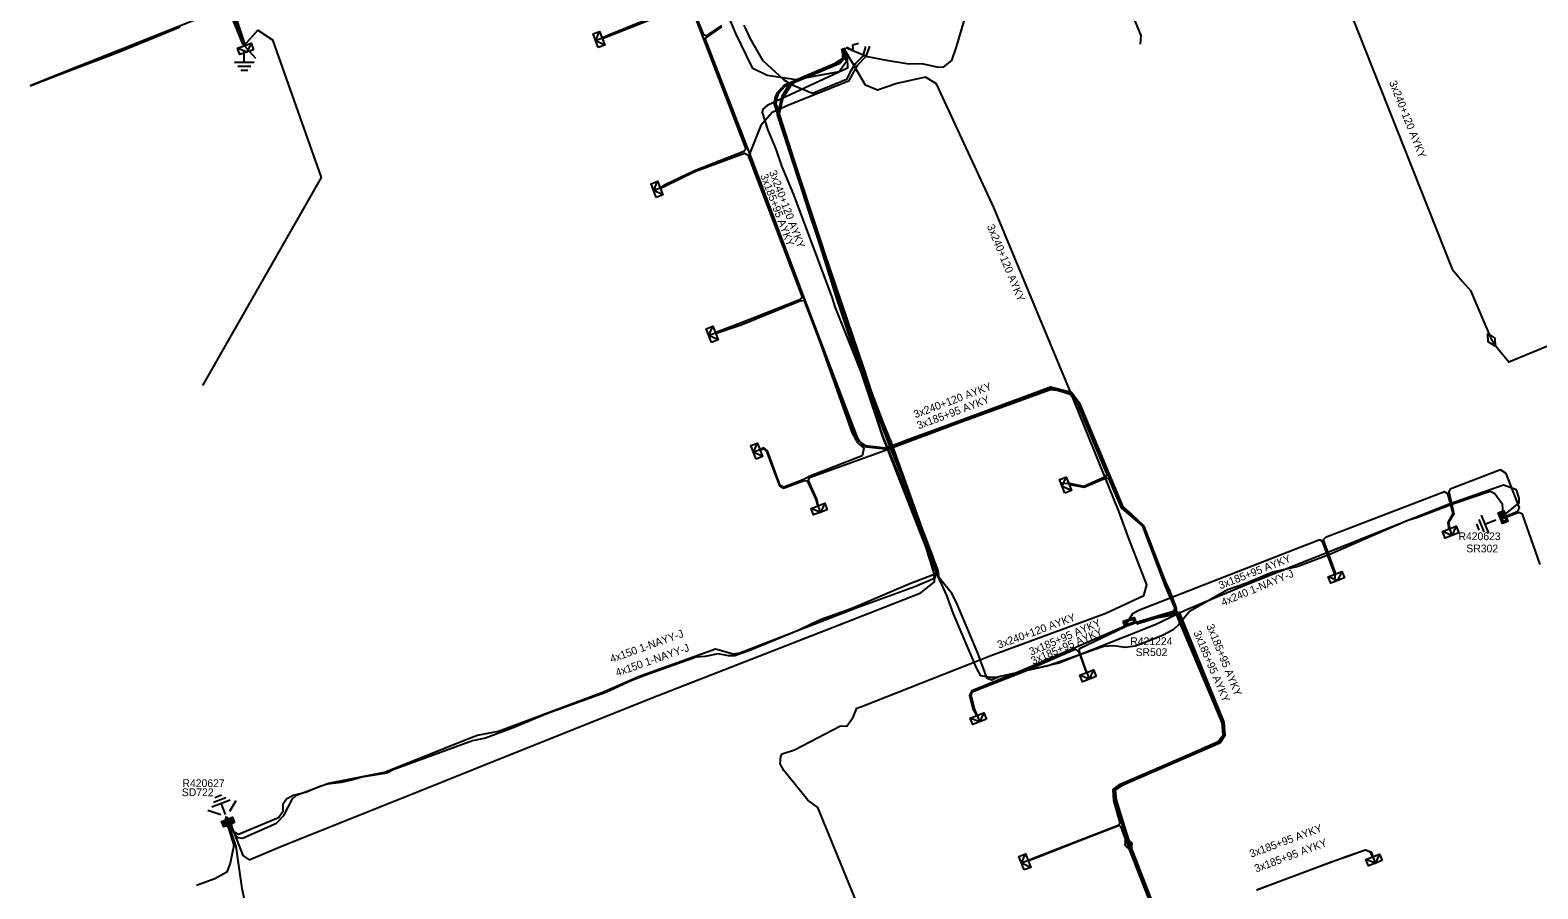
# Model space of a CAD drawing. Extents: x -540028 to -538776, y -1157064 to -1155670.
# Drawn here: x -540028.2 to -539834.1, y -1156040.4 to -1155929.9 of the extents above; entities that cross this region are included whole.
import ezdxf

# ---------------------------------------------------------------- set-up
doc = ezdxf.new("R2010")
doc.units = 0
for name, color, linetype in [('Vrstva 15', 7, 'Continuous'), ('Vrstva 19', 7, 'Continuous'), ('Vrstva 2', 7, 'Continuous'), ('Vrstva 28', 7, 'Continuous'), ('Vrstva 29', 7, 'Continuous'), ('Vrstva 30', 7, 'Continuous'), ('Vrstva 31', 7, 'Continuous'), ('Vrstva 5', 7, 'Continuous'), ('Vrstva 59', 7, 'Continuous'), ('Vrstva 6', 7, 'Continuous'), ('Vrstva 9', 7, 'Continuous')]:
    doc.layers.add(name, color=color, linetype=linetype)

# ---------------------------------------------------------------- blocks, each defined once
blk = doc.blocks.new('17')
at = {"layer": 'Vrstva 2'}
blk.add_lwpolyline([(-1.875, 0), (0, 0.9375), (1.875, 0), (0, -0.9375)], close=True, dxfattribs=at)
blk = doc.blocks.new('132')
at = {"layer": 'Vrstva 2'}
for points in [[(-1.5, 1.5), (1.5, 1.5), (1.5, 0), (-1.5, 0)], [(-1.1, 1.2), (1.1, 1.2), (1.1, 0.3), (-1.1, 0.3)]]:
    blk.add_lwpolyline(points, close=True, dxfattribs=at)
blk = doc.blocks.new('23')
at = {"layer": 'Vrstva 2'}
blk.add_lwpolyline([(1.875, -1.8), (-1.875, -1.8), (-1.875, 0), (1.875, 0)], close=True, dxfattribs=at)
blk.add_lwpolyline([(1.875, 0), (0, -1.8), (-1.875, 0)], dxfattribs=at)
blk = doc.blocks.new('11')
at = {"layer": 'Vrstva 2'}
for p, q in [((0, -4.3), (0, -1.3)), ((-2.5, -4.3), (2.5, -4.3)), ((-1.7, -5.3), (1.7, -5.3)), ((-0.9, -6.3), (0.9, -6.3))]:
    blk.add_line(p, q, dxfattribs=at)

msp = doc.modelspace()

# ---------------------------------------------------------------- linework, layer by layer
at = {"layer": 'Vrstva 5'}
for points in [[(-539923.21, -1155932.13), (-539920.48, -1155933.29), (-539917.96, -1155933.77), (-539915.09, -1155934.22), (-539913.44, -1155934.2), (-539911.31, -1155934.66), (-539910.61, -1155934.6), (-539909.58, -1155933.81), (-539908.94, -1155932.04), (-539907.91, -1155928.58), (-539907.39, -1155927.03), (-539906.62, -1155924.35), (-539904.52, -1155923.13), (-539902.28, -1155922.05), (-539874.21, -1155910.19), (-539872.95, -1155910.4), (-539871.83, -1155912.86), (-539873.27, -1155917.34)], [(-539864.72, -1155912.09), (-539858.4, -1155927.24), (-539845.14, -1155960.66), (-539843.86, -1155962.22), (-539842.78, -1155963.39), (-539840.09, -1155969.77)], [(-539873.57, -1155917.46), (-539874.09, -1155917.04), (-539877.68, -1155918.43), (-539881.42, -1155919.95), (-539886.16, -1155922.38), (-539886.77, -1155923.05), (-539887.27, -1155924.13), (-539886.55, -1155927.38), (-539885.24, -1155930.57)], [(-539941.93, -1155919.51), (-539937.39, -1155930.32), (-539935.25, -1155934.75), (-539933.32, -1155935.67), (-539929.58, -1155936.26), (-539924.07, -1155935.23), (-539923.12, -1155933.89), (-539923.63, -1155932.32)], [(-540002.3, -1155927.48), (-540000.64, -1155931.61), (-540000.64, -1155931.88), (-540000.83, -1155931.68), (-540002.5, -1155927.53)], [(-539943.66, -1155926.44), (-539953.55, -1155930.43), (-539954.55, -1155930.88), (-539954.57, -1155930.93), (-539954.51, -1155930.95), (-539943.67, -1155926.69)], [(-539943.15, -1155926.79), (-539936.08, -1155945.19), (-539936.32, -1155945.51), (-539942.68, -1155948), (-539946.45, -1155949.81), (-539947.07, -1155950.17), (-539947.1, -1155950.22), (-539947.04, -1155950.24), (-539946.42, -1155949.92), (-539942.64, -1155948.07), (-539936.26, -1155945.71), (-539935.8, -1155945.95), (-539928.83, -1155964.25), (-539929.04, -1155964.58), (-539936.76, -1155967.61), (-539939.93, -1155968.81), (-539939.99, -1155968.88), (-539939.89, -1155968.9), (-539936.69, -1155967.81), (-539928.99, -1155964.7), (-539928.59, -1155964.75), (-539926.53, -1155970.16), (-539922.4, -1155981.76), (-539921.73, -1155982.93), (-539920.87, -1155983.76), (-539921.1, -1155984.67), (-539927.91, -1155987.35), (-539928.63, -1155987.72), (-539931.17, -1155988.73), (-539931.64, -1155988.5), (-539933.29, -1155984.03), (-539933.76, -1155983.65), (-539934.23, -1155983.87), (-539934.26, -1155983.91), (-539934.2, -1155983.93), (-539933.75, -1155983.79), (-539933.41, -1155984.11), (-539931.74, -1155988.56), (-539931.21, -1155988.85), (-539928.55, -1155987.84), (-539928.17, -1155987.91), (-539927.06, -1155990.29), (-539926.86, -1155991.07), (-539926.8, -1155991.12), (-539926.75, -1155991.04), (-539926.95, -1155990.27), (-539928.02, -1155987.86), (-539927.87, -1155987.48), (-539918.1, -1155983.96), (-539908.71, -1155980.43), (-539896.84, -1155976.14), (-539896.01, -1155976.23), (-539894.33, -1155976.73), (-539893.44, -1155977.96), (-539889.59, -1155987.09), (-539889.79, -1155987.4), (-539892.57, -1155988.64), (-539894.38, -1155988.24), (-539894.5, -1155988.29)], [(-539939.2, -1155929.31), (-539941.17, -1155930.62), (-539941.49, -1155930.5), (-539943.08, -1155926.61)], [(-540008.91, -1155929.5), (-540013.7, -1155931.47), (-540016.97, -1155932.82), (-540024.56, -1155935.68), (-540028.19, -1155937.12)], [(-539885.8, -1156006.24), (-539885.73, -1156006.15), (-539883.25, -1156005.41), (-539880.93, -1156004.8), (-539880.62, -1156004.29), (-539881.44, -1156002.1), (-539882.01, -1156000.96), (-539884.82, -1155993.72), (-539887.66, -1155991.28), (-539893.31, -1155977.89), (-539893.62, -1155977.46), (-539894.24, -1155976.6), (-539895.98, -1155976.08), (-539896.86, -1155975.98), (-539908.76, -1155980.29), (-539918.15, -1155983.82), (-539920.91, -1155983.51), (-539921.63, -1155982.56), (-539923.73, -1155977.05), (-539928.51, -1155964.45), (-539935.45, -1155946.09), (-539941.33, -1155930.97), (-539939.17, -1155929.47)], [(-539920.68, -1155932), (-539921.01, -1155933.25), (-539922.01, -1155934.24), (-539922.67, -1155935.36), (-539923.12, -1155936.25), (-539927.48, -1155938.03), (-539930.1, -1155936.98), (-539931.19, -1155936.29), (-539933.83, -1155933.83), (-539935.5, -1155930.94), (-539936.28, -1155929.23)], [(-540002.86, -1156031.48), (-540001.9, -1156033.37), (-540001.46, -1156033.81), (-540000.89, -1156033.88), (-539996.48, -1156031.96), (-539995.54, -1156030.98), (-539994.43, -1156028.84), (-539993.92, -1156028.37), (-539989.78, -1156026.81), (-539982.58, -1156025.41), (-539971.29, -1156020.9), (-539970.62, -1156020.66), (-539967.91, -1156020.14), (-539954.61, -1156015.14), (-539951.06, -1156013.6), (-539949.9, -1156013.11), (-539939.99, -1156009.53), (-539937.72, -1156010.17), (-539936.86, -1156010.06), (-539928.3, -1156006.73), (-539927.2, -1156006.3), (-539922.98, -1156004.69), (-539921.87, -1156004.27), (-539914.32, -1156001.49), (-539911.72, -1156000.38), (-539911.48, -1155999.5), (-539913.12, -1155995.28), (-539917.5, -1155983.04), (-539918.6, -1155980.42), (-539920.06, -1155976.46), (-539920.99, -1155973.68), (-539927.61, -1155954.25), (-539932.37, -1155939.41), (-539932.29, -1155938.6), (-539932, -1155937.9), (-539931.12, -1155936.94), (-539924.07, -1155933.98), (-539923.6, -1155933.49), (-539923.58, -1155932.92), (-539923.7, -1155932.31)], [(-539923.36, -1155932.19), (-539923.02, -1155933.47), (-539922.98, -1155934.78), (-539933.33, -1155939.61), (-539933.89, -1155940.04), (-539933.98, -1155940.47), (-539933.23, -1155942.76), (-539932.23, -1155945.21), (-539931.49, -1155947.35), (-539929.9, -1155951.17), (-539925.01, -1155964.27), (-539924.6, -1155965.5), (-539919.91, -1155977.31), (-539918.8, -1155980.31), (-539917.52, -1155983.59), (-539915.31, -1155989.07), (-539912.04, -1155997.59), (-539911.57, -1155999.4), (-539911.7, -1155999.9), (-539914.96, -1156001.16), (-539922, -1156004.16), (-539923.11, -1156004.61), (-539926.4, -1156005.74), (-539927.6, -1156006.29), (-539929.36, -1156007.18), (-539935.35, -1156009.66), (-539937.49, -1156010.45), (-539938.33, -1156010.42), (-539939.62, -1156010.19), (-539941.3, -1156010.5), (-539942.46, -1156010.62), (-539949.06, -1156012.95), (-539950.77, -1156013.6), (-539954.09, -1156015.14), (-539961.61, -1156017.84), (-539966.03, -1156019.7), (-539969.58, -1156021.02), (-539971.25, -1156021.37), (-539981.48, -1156025.1), (-539982.28, -1156025.54), (-539985.45, -1156026.03), (-539986.65, -1156026.41), (-539988.15, -1156026.75), (-539989.91, -1156026.96), (-539990.9, -1156027.27), (-539992.62, -1156027.98), (-539994.33, -1156028.42), (-539995.19, -1156028.9), (-539995.67, -1156029.56), (-539995.67, -1156030.49), (-539996.24, -1156031.28), (-540001.37, -1156033.41), (-540001.93, -1156033.12), (-540002.69, -1156032.12), (-540002.82, -1156031.42)], [(-539920.15, -1155931.97), (-539920.61, -1155933.3), (-539921.76, -1155934.44), (-539922.85, -1155936.45), (-539930.67, -1155939.59), (-539932.7, -1155940.49), (-539934.14, -1155942.16), (-539935.53, -1155945.58), (-539935.59, -1155946.31), (-539931.97, -1155955.71), (-539926.81, -1155969.18), (-539922.75, -1155980.21), (-539921.77, -1155982.63), (-539920.72, -1155983.34), (-539918.1, -1155983.67), (-539916.23, -1155982.95), (-539915.56, -1155982.71), (-539910.16, -1155980.73), (-539896.84, -1155975.82), (-539894.17, -1155976.51), (-539893.16, -1155977.83), (-539887.55, -1155991.23), (-539886.4, -1155992.22), (-539884.98, -1155993.56), (-539882.11, -1156001.17), (-539874.7, -1156019.01), (-539874.55, -1156020.64), (-539875.2, -1156021.54), (-539887.83, -1156027.04), (-539888.69, -1156027.65), (-539888.61, -1156029.01), (-539887.02, -1156034.15), (-539886.66, -1156035.08), (-539882.13, -1156046.77)], [(-539838.94, -1155992.7), (-539838.57, -1155992), (-539838.67, -1155990.93), (-539839.67, -1155989.57), (-539840.28, -1155989.26), (-539845.08, -1155990.9), (-539849.71, -1155992.66), (-539850.84, -1155993.03), (-539856.32, -1155995.35), (-539860.88, -1155997.4), (-539864.98, -1155998.94), (-539868.24, -1155999.66), (-539871.7, -1156001.11), (-539874.07, -1156001.95), (-539878.95, -1156004.71), (-539880.38, -1156006.42), (-539881.07, -1156007.09), (-539882.43, -1156007.81), (-539884.71, -1156008.71), (-539885.96, -1156009.18), (-539887.23, -1156009.36), (-539888.69, -1156009.16), (-539889.99, -1156009.23), (-539892.61, -1156010.13), (-539897.15, -1156011.72), (-539903.5, -1156013.14), (-539904.43, -1156013.57), (-539905.02, -1156013.34), (-539906.23, -1156010.07), (-539908.89, -1156003.8), (-539909.5, -1156002.45), (-539911.18, -1156000.39), (-539911.3, -1155999.43), (-539912.94, -1155995.21), (-539917.32, -1155982.96), (-539918.42, -1155980.34), (-539919.88, -1155976.4), (-539920.81, -1155973.62), (-539927.43, -1155954.19), (-539932.17, -1155939.39), (-539932.09, -1155938.66), (-539931.82, -1155938), (-539931, -1155937.1), (-539923.95, -1155934.14), (-539923.4, -1155933.57), (-539923.38, -1155932.9), (-539923.51, -1155932.23)], [(-539920.99, -1156044.18), (-539926.8, -1156029.97), (-539928.09, -1156029.01), (-539931.17, -1156025.2), (-539931.64, -1156024.33), (-539931.56, -1156023.35), (-539931.38, -1156023.04), (-539929.82, -1156022.55), (-539923.9, -1156019.44), (-539923.08, -1156019.48), (-539922.27, -1156018.32), (-539921.78, -1156017.16), (-539921.06, -1156016.91), (-539904.39, -1156010.35), (-539889.73, -1156004.95), (-539884.83, -1156002.66), (-539884.47, -1156001.31), (-539886.77, -1155995.32), (-539888.06, -1155991.82), (-539894.41, -1155976.16), (-539898.67, -1155965.95), (-539904.15, -1155952.71), (-539911.52, -1155936.82), (-539912.96, -1155935.94), (-539916.65, -1155936.75), (-539919.11, -1155937.63), (-539920.66, -1155936.96), (-539923.45, -1155932.23)], [(-539923.09, -1155932.09), (-539922.53, -1155932.4), (-539922.27, -1155932.3), (-539922.32, -1155931.8)], [(-539830.05, -1155969.43), (-539837.85, -1155972.64), (-539839.26, -1155970.91), (-539840.09, -1155969.77)], [(-539894.5, -1155988.29), (-539894.4, -1155988.37), (-539892.52, -1155988.72), (-539889.71, -1155987.53), (-539889.38, -1155987.6), (-539887.78, -1155991.38), (-539885.02, -1155993.73), (-539882.07, -1156001.57), (-539880.86, -1156004.34), (-539881.06, -1156004.73), (-539885.82, -1156006.13), (-539885.83, -1156006.16)], [(-539838.94, -1155992.76), (-539836.68, -1155991.82), (-539836.48, -1155991.37), (-539838.19, -1155986.97), (-539838.95, -1155986.48), (-539845.41, -1155988.96), (-539845.59, -1155989.28), (-539844.93, -1155992.14), (-539845.61, -1155993.27), (-539845.5, -1155993.94), (-539845.51, -1155994.1), (-539845.56, -1155993.94), (-539845.66, -1155993.25), (-539845.02, -1155992.12), (-539845.71, -1155989.56), (-539846.14, -1155989.3), (-539861.44, -1155995.21), (-539861.74, -1155995.49), (-539860.22, -1155999.76), (-539860.23, -1155999.9)], [(-539833.81, -1155998.68), (-539836.11, -1155992.19), (-539836.57, -1155991.96), (-539838.89, -1155992.88)], [(-539860.23, -1155999.9), (-539860.32, -1155999.82), (-539861.85, -1155995.72), (-539862.19, -1155995.48), (-539865.4, -1155996.73), (-539885.39, -1156004.56), (-539886.31, -1156005.01), (-539887.27, -1156006.59), (-539893.2, -1156009.18), (-539900.4, -1156012.27), (-539907, -1156014.93), (-539907.29, -1156015.48), (-539906.84, -1156017.26), (-539906.34, -1156018.1), (-539906.32, -1156018.1), (-539906.31, -1156018.08), (-539906.64, -1156017.2), (-539907.05, -1156015.53), (-539906.96, -1156015.08), (-539900.29, -1156012.44), (-539893.68, -1156009.59), (-539893.22, -1156009.91), (-539892.25, -1156012.56), (-539892.2, -1156012.59), (-539892.17, -1156012.53), (-539892.59, -1156011.39), (-539893.13, -1156009.87), (-539893.14, -1156009.49), (-539887.28, -1156006.7)], [(-539883.66, -1156043.14), (-539886.91, -1156034.8), (-539887.77, -1156032.5), (-539887.99, -1156032.29), (-539893.1, -1156034.26), (-539898.61, -1156036.42), (-539899.68, -1156036.81), (-539899.75, -1156036.79), (-539899.73, -1156036.72), (-539898.65, -1156036.32), (-539893.14, -1156034.17), (-539888.03, -1156032.2), (-539887.87, -1156031.92), (-539888.71, -1156029.04), (-539888.78, -1156027.64), (-539887.88, -1156026.95), (-539880.33, -1156023.68), (-539875.26, -1156021.45), (-539874.62, -1156020.6), (-539874.77, -1156019.04), (-539880.66, -1156005.12), (-539883.23, -1156005.6), (-539885.62, -1156006.32), (-539885.72, -1156006.45)], [(-539885.76, -1156006.34), (-539885.65, -1156006.23), (-539883.25, -1156005.48), (-539880.3, -1156004.8), (-539874.53, -1156018.98), (-539874.42, -1156020.7), (-539875.07, -1156021.69), (-539887.72, -1156027.18), (-539888.54, -1156027.71), (-539888.41, -1156028.97), (-539887.55, -1156031.77), (-539886.51, -1156035), (-539882.48, -1156045.43)], [(-540003.04, -1156031.53), (-540002.84, -1156032.07), (-540002, -1156034.83), (-540002.45, -1156037.1), (-540002.91, -1156038.29), (-540004.45, -1156039.14), (-540006.79, -1156039.98)], [(-540002.68, -1156032.01), (-540002.92, -1156031.47)], [(-540002, -1156063.03), (-539999.22, -1156062.13), (-539997.22, -1156060.88), (-539996.66, -1156059.27), (-539997.35, -1156055.47), (-539998.23, -1156051.74), (-539998.43, -1156049.71), (-539999.71, -1156046.23), (-540000.93, -1156040.38), (-540001.68, -1156034.96), (-540002.68, -1156032.01)], [(-539870.33, -1156040.53), (-539858.6, -1156036.19), (-539856.32, -1156035.39), (-539855.59, -1156035.68), (-539855.38, -1156036.28), (-539855.38, -1156036.3), (-539855.4, -1156036.28), (-539855.66, -1156035.7), (-539856.34, -1156035.45), (-539858.58, -1156036.24), (-539860.58, -1156036.96), (-539870.3, -1156040.6)]]:
    msp.add_lwpolyline(points, dxfattribs=at)
at = {"layer": 'Vrstva 59'}
for points in [[(-540000.64, -1155931.88), (-539998.9, -1155929.91), (-539997, -1155931.15), (-539990.73, -1155948.86), (-540006.04, -1155975.62)], [(-539954.57, -1155930.93), (-539955.51, -1155931.29)], [(-539922.32, -1155931.8), (-539921.57, -1155931.58)], [(-539885.24, -1155930.57), (-539885.32, -1155931.68)], [(-540000.64, -1155931.88), (-539999.2, -1155933.49)], [(-539947.1, -1155950.22), (-539948.04, -1155950.57)], [(-539939.99, -1155968.88), (-539940.92, -1155969.24)], [(-539934.26, -1155983.91), (-539935.19, -1155984.27)], [(-539894.5, -1155988.29), (-539895.61, -1155988.19)], [(-539926.8, -1155991.12), (-539926.44, -1155992.05)], [(-539845.51, -1155994.1), (-539845.14, -1155995.03)], [(-539860.23, -1155999.9), (-539860.33, -1156001.01)], [(-539892.2, -1156012.59), (-539891.84, -1156013.52)], [(-539906.32, -1156018.1), (-539905.95, -1156019.03)], [(-540003.67, -1156030.89), (-540005.32, -1156030.34)], [(-540002.52, -1156030.44), (-540001.7, -1156029.05)], [(-539855.38, -1156036.3), (-539855.02, -1156037.23)], [(-539899.75, -1156036.79), (-539900.68, -1156037.16)]]:
    msp.add_lwpolyline(points, dxfattribs=at)
at = {"layer": 'Vrstva 9'}
for points in [[(-540028.21, -1155937.02), (-540024.81, -1155935.64), (-540016.61, -1155932.38), (-540004.35, -1155927.48)], [(-540002.15, -1155927.87), (-540000.6, -1155931.77), (-540000.56, -1155931.79), (-540000.53, -1155931.74), (-540001.9, -1155927.61)], [(-540002.17, -1156032.72), (-540000.85, -1156036.12), (-540000.01, -1156036.69), (-539995.44, -1156034.76), (-539978.98, -1156028.2), (-539966.71, -1156023.28), (-539947.51, -1156015.56), (-539922.32, -1156005.75), (-539913.54, -1156002.3), (-539911.81, -1156000.91), (-539911.83, -1155999.82), (-539912.86, -1155996.5), (-539918.46, -1155982.25), (-539924.45, -1155964.18), (-539926.39, -1155957.99), (-539932, -1155940.78), (-539931.39, -1155938.38), (-539930.53, -1155936.96), (-539929.65, -1155936.28), (-539924.57, -1155934.15), (-539923.49, -1155933.45), (-539923.36, -1155932.83), (-539923.57, -1155932.3)], [(-539838.9, -1155992.68), (-539836.52, -1155990.73), (-539836.51, -1155990.12), (-539836.87, -1155989.05), (-539838.53, -1155988.45), (-539845.52, -1155990.89), (-539871.84, -1156001.38), (-539879.45, -1156004.57), (-539883.37, -1156006.44), (-539895.8, -1156011.38), (-539903.85, -1156013.23), (-539904.59, -1156013.2), (-539905.82, -1156013.01), (-539906.37, -1156011.98), (-539909.35, -1156005.01), (-539910.19, -1156002.68), (-539911.54, -1155999.74), (-539914.4, -1155991.84), (-539918.39, -1155982.26), (-539924.37, -1155964.15), (-539926.16, -1155957.8), (-539931.77, -1155940.73), (-539931.26, -1155938.56), (-539930.3, -1155937.04), (-539929.41, -1155936.29), (-539924.51, -1155934.28), (-539923.43, -1155933.46), (-539923.26, -1155932.73), (-539923.53, -1155932.26)], [(-540002.71, -1156031.31), (-540002.17, -1156032.72)]]:
    msp.add_lwpolyline(points, dxfattribs=at)

# ---------------------------------------------------------------- block references
at = {"layer": 'Vrstva 15', "xscale": 0.5, "yscale": 0.5}
msp.add_blockref('11', (-540000.64, -1155931.88), dxfattribs=at)
at = {"layer": 'Vrstva 15'}
for p, xscale, yscale, rotation in [((-539838.94, -1155992.7), 0.49999999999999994, 0.5000000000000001, -68.48933332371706), ((-540002.86, -1156031.48), 0.5, 0.49999999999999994, -158.7815499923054)]:
    msp.add_blockref('11', p, dxfattribs=dict(at, xscale=xscale, yscale=yscale, rotation=rotation))
at = {"layer": 'Vrstva 19', "xscale": 0.5, "yscale": 0.5}
for p, rotation in [((-539840.09, -1155969.77), -60.901705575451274), ((-540002.68, -1156032), -71.4348555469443), ((-539886.81, -1156034.68), -68.71983336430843)]:
    msp.add_blockref('17', p, dxfattribs=dict(at, rotation=rotation))
at = {"layer": 'Vrstva 28'}
for p, xscale, yscale, rotation in [((-539838.94, -1155992.7), 0.49999999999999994, 0.5000000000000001, -68.48933332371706), ((-539886.55, -1156006.44), 0.5, 0.5, 19.766536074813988), ((-540002.86, -1156031.48), 0.5, 0.5000000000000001, -158.26336167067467)]:
    msp.add_blockref('132', p, dxfattribs=dict(at, xscale=xscale, yscale=yscale, rotation=rotation))
at = {"layer": 'Vrstva 31'}
for p, xscale, yscale, rotation in [((-540000.64, -1155931.88), 0.5, 0.49999999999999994, 19.86837223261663), ((-539954.57, -1155930.93), 0.5, 0.5, -69.01018334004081), ((-539947.1, -1155950.22), 0.49999999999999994, 0.5000000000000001, -69.29247776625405), ((-539939.99, -1155968.88), 0.49999999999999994, 0.5000000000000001, -68.92459724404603), ((-539934.26, -1155983.91), 0.5, 0.5, -68.94524173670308), ((-539894.5, -1155988.29), 0.5, 0.5, -68.58318614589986), ((-539926.8, -1155991.12), 0.49999999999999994, 0.5000000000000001, 21.146627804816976), ((-539845.51, -1155994.1), 0.5, 0.5, 21.605747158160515), ((-539860.23, -1155999.9), 0.5, 0.5, 21.547544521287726), ((-539892.2, -1156012.59), 0.5, 0.49999999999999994, 21.428786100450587), ((-539906.32, -1156018.1), 0.5, 0.5000000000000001, 21.425341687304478), ((-539899.75, -1156036.79), 0.49999999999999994, 0.5000000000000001, -68.27450564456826), ((-539855.38, -1156036.3), 0.49999999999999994, 0.5000000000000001, 21.60288329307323)]:
    msp.add_blockref('23', p, dxfattribs=dict(at, xscale=xscale, yscale=yscale, rotation=rotation))

# ---------------------------------------------------------------- texts
at = {"layer": 'Vrstva 29'}
for s, p in [('R420623', (-539844.34, -1155995.54)), ('R421224', (-539886.59, -1156009.05))]:
    msp.add_text(s, height=1, dxfattribs=at).set_placement(p)
msp.add_text('R420627', height=1, rotation=359.933, dxfattribs=at).set_placement((-540008.6, -1156027.32))
at = {"layer": 'Vrstva 30'}
for s, rotation, p in [('SR302', 359.787, (-539843.33, -1155997.1)), ('SR502', 0.047, (-539885.9, -1156010.46)), ('SD722', 359.933, (-540008.68, -1156028.49))]:
    msp.add_text(s, height=1, rotation=rotation, dxfattribs=at).set_placement(p)
at = {"layer": 'Vrstva 6'}
for s, rotation, p in [('3x240+120 AYKY', 291.629, (-539853.29, -1155936.61)), ('3x185+95 AYKY', 290.84, (-539934.24, -1155948.6)), ('3x240+120 AYKY', 290.723, (-539933.11, -1155948.15)), ('3x240+120 AYKY', 292.466, (-539905.07, -1155955.12)), ('3x240+120 AYKY', 20.605, (-539914.25, -1155979.86)), ('3x185+95 AYKY', 20.627, (-539913.83, -1155981.29)), ('3x185+95 AYKY', 21.394, (-539874.99, -1156001.88)), ('4x240 1-NAYY-J', 22.737, (-539874.64, -1156004.05)), ('3x240+120 AYKY', 20.219, (-539903.49, -1156009.52)), ('4x150 1-NAYY-J', 19.862, (-539953.36, -1156011.34)), ('3x185+95 AYKY', 23.269, (-539899.35, -1156010.42)), ('3x185+95 AYKY', 23.313, (-539899.12, -1156011.58)), ('3x185+95 AYKY', 292.95, (-539878.48, -1156007.43)), ('3x185+95 AYKY', 292.123, (-539876.82, -1156006.57)), ('4x150 1-NAYY-J', 19.445, (-539952.65, -1156013.1)), ('3x185+95 AYKY', 20.304, (-539871.02, -1156036.42)), ('3x185+95 AYKY', 20.525, (-539870.39, -1156038.33))]:
    msp.add_text(s, height=1, rotation=rotation, dxfattribs=at).set_placement(p)

doc.saveas('drawing.dxf')
